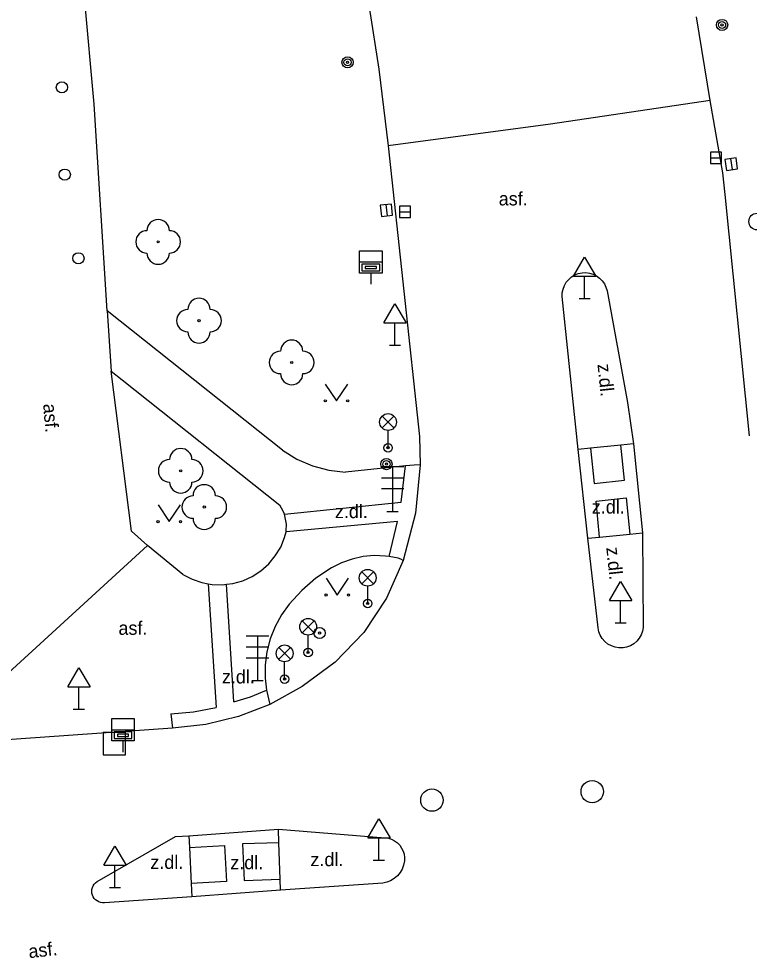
# Model space of a CAD drawing. Extents: x -642282 to -641982, y -1041678 to -1041427.
# Drawn here: x -642202.75 to -642170.13, y -1041575.81 to -1041533.81 of the extents above; entities that cross this region are included whole.
import ezdxf

# ---------------------------------------------------------------- set-up
doc = ezdxf.new("R2010")
doc.units = 0
for name, color, linetype in [('Popis povrchů', 7, 'Continuous'), ('Rozhraní ploch 1', 7, 'Continuous'), ('Rozhraní ploch 2', 7, 'Continuous'), ('Sloupy_označník', 7, 'Continuous'), ('Zeleň - stromy', 7, 'Continuous'), ('Znaky doprava', 7, 'Continuous'), ('Znaky kanalizace', 7, 'Continuous'), ('Znaky plyn', 7, 'Continuous'), ('Znaky voda', 7, 'Continuous'), ('Značky doprava', 7, 'Continuous'), ('Značky KM', 7, 'Continuous'), ('Šachty ner_', 7, 'Continuous')]:
    doc.layers.add(name, color=color, linetype=linetype)

msp = doc.modelspace()

# ---------------------------------------------------------------- linework, layer by layer
at = {"layer": 'Rozhraní ploch 1'}
for p, q in [((-642199.383, -1041537.636), (-642201.296, -1041516.368)), ((-642187.098, -1041533.3), (-642186.671, -1041536.073)), ((-642171.87, -1041537.46), (-642172.48, -1041533.728)), ((-642186.671, -1041536.073), (-642186.25, -1041539.49)), ((-642198.8, -1041546.87), (-642199.383, -1041537.636)), ((-642177.77, -1041553.07), (-642178.48, -1041546.23)), ((-642176.48, -1041545.98), (-642175.56, -1041550.96)), ((-642190.97, -1041553.1), (-642198.8, -1041546.87)), ((-642197.72, -1041556.72), (-642198.63, -1041549.56)), ((-642198.13, -1041549.95), (-642191.1, -1041555.56)), ((-642175.56, -1041550.96), (-642175.3, -1041552.81)), ((-642197.72, -1041556.72), (-642197.01, -1041557.36)), ((-642195.42, -1041558.65), (-642197.01, -1041557.36))]:
    msp.add_line(p, q, dxfattribs=at)
for points in [[(-642171.2, -1041541.67), (-642171.3, -1041540.7), (-642171.87, -1041537.46)], [(-642186.25, -1041539.49), (-642184.86, -1041552.48)], [(-642170.12, -1041552.46), (-642171.2, -1041541.67)], [(-642178.48, -1041546.23), (-642178.476, -1041546.061), (-642178.443, -1041545.896), (-642178.384, -1041545.738), (-642178.299, -1041545.592), (-642178.191, -1041545.463), (-642178.063, -1041545.353), (-642177.919, -1041545.266), (-642177.762, -1041545.204), (-642177.597, -1041545.169), (-642177.428, -1041545.162), (-642177.261, -1041545.184), (-642177.1, -1041545.232), (-642176.949, -1041545.307), (-642176.812, -1041545.406), (-642176.694, -1041545.527), (-642176.598, -1041545.665), (-642176.526, -1041545.818), (-642176.48, -1041545.98)], [(-642184.86, -1041552.48), (-642184.83, -1041553.75), (-642185.039, -1041555.919), (-642185.58, -1041558.03), (-642186.322, -1041559.713), (-642187.345, -1041561.243)], [(-642175.3, -1041552.81), (-642174.9, -1041556.79), (-642174.86, -1041561.02), (-642174.892, -1041561.192), (-642174.953, -1041561.355), (-642175.041, -1041561.506), (-642175.154, -1041561.639), (-642175.287, -1041561.752), (-642175.438, -1041561.839), (-642175.602, -1041561.9), (-642175.76, -1041561.93), (-642175.948, -1041561.933), (-642176.121, -1041561.905)], [(-642190.97, -1041553.1), (-642190.327, -1041553.493), (-642189.64, -1041553.79), (-642188.908, -1041553.988), (-642188.16, -1041554.08)], [(-642176.121, -1041561.905), (-642176.286, -1041561.848), (-642176.438, -1041561.763), (-642176.574, -1041561.654), (-642176.689, -1041561.522), (-642176.78, -1041561.373), (-642176.845, -1041561.211), (-642176.88, -1041561.04), (-642177.34, -1041557.03), (-642177.77, -1041553.07)], [(-642184.83, -1041553.75), (-642185.1, -1041553.76), (-642185.477, -1041553.799), (-642188.16, -1041554.08)], [(-642190.88, -1041557), (-642190.818, -1041556.743), (-642190.813, -1041556.706), (-642190.802, -1041556.404), (-642190.848, -1041556.106), (-642190.892, -1041555.958), (-642190.948, -1041555.821), (-642191.1, -1041555.56)], [(-642195.42, -1041558.65), (-642195.01, -1041558.866), (-642194.572, -1041559.017), (-642194.29, -1041559.07), (-642194.116, -1041559.1), (-642193.653, -1041559.114), (-642193.47, -1041559.09), (-642193.193, -1041559.058), (-642192.747, -1041558.933), (-642192.325, -1041558.742), (-642191.936, -1041558.49), (-642191.59, -1041558.182), (-642191.295, -1041557.826), (-642191.056, -1041557.429), (-642190.88, -1041557)], [(-642186.37, -1041557.83), (-642186.873, -1041557.81), (-642187.375, -1041557.854), (-642187.867, -1041557.962), (-642188.341, -1041558.131), (-642188.79, -1041558.36)], [(-642185.81, -1041557.92), (-642186.209, -1041557.856), (-642186.37, -1041557.83)], [(-642185.58, -1041558.03), (-642185.689, -1041557.962), (-642185.81, -1041557.92)], [(-642188.79, -1041558.36), (-642189.479, -1041558.825), (-642190.108, -1041559.368), (-642190.67, -1041559.98)], [(-642190.67, -1041559.98), (-642191.016, -1041560.462), (-642191.3, -1041560.983), (-642191.518, -1041561.535), (-642191.667, -1041562.11), (-642191.744, -1041562.698), (-642191.749, -1041563.292), (-642191.691, -1041563.821), (-642191.681, -1041563.882), (-642191.54, -1041564.458)], [(-642187.345, -1041561.243), (-642188.617, -1041562.572), (-642190.1, -1041563.66), (-642191.54, -1041564.458), (-642192.94, -1041565), (-642194.398, -1041565.356), (-642195.89, -1041565.52)], [(-642195.89, -1041565.52), (-642211.74, -1041566.64)], [(-642199.26, -1041572.38), (-642195.76, -1041570.37), (-642195.16, -1041570.33), (-642191.16, -1041570.04)], [(-642191.16, -1041570.04), (-642186.39, -1041570.42), (-642186.242, -1041570.444), (-642186.099, -1041570.491), (-642185.965, -1041570.561), (-642185.845, -1041570.65)], [(-642185.845, -1041570.65), (-642185.74, -1041570.758), (-642185.654, -1041570.881), (-642185.588, -1041571.017), (-642185.545, -1041571.161), (-642185.526, -1041571.31), (-642185.53, -1041571.46), (-642185.566, -1041571.643), (-642185.631, -1041571.818), (-642185.725, -1041571.979), (-642185.844, -1041572.123), (-642185.985, -1041572.245), (-642186.144, -1041572.341), (-642186.318, -1041572.411), (-642186.5, -1041572.45), (-642191.06, -1041572.77)], [(-642191.06, -1041572.77), (-642195.02, -1041573.06), (-642198.93, -1041573.33), (-642199.015, -1041573.33), (-642199.1, -1041573.316), (-642199.181, -1041573.288), (-642199.256, -1041573.247), (-642199.323, -1041573.195), (-642199.381, -1041573.132), (-642199.428, -1041573.061), (-642199.463, -1041572.983), (-642199.484, -1041572.9), (-642199.491, -1041572.815), (-642199.485, -1041572.73), (-642199.464, -1041572.647), (-642199.431, -1041572.568), (-642199.384, -1041572.496), (-642199.327, -1041572.433), (-642199.26, -1041572.38)]]:
    msp.add_lwpolyline(points, dxfattribs=at)
at = {"layer": 'Rozhraní ploch 2'}
for p, q in [((-642185.68, -1041555.42), (-642185.477, -1041553.799)), ((-642190.892, -1041555.958), (-642185.68, -1041555.42)), ((-642197.01, -1041557.36), (-642203.39, -1041563.21)), ((-642194.29, -1041559.07), (-642193.94, -1041564.6)), ((-642193.15, -1041564.35), (-642193.47, -1041559.09)), ((-642195.96, -1041564.88), (-642195.89, -1041565.52))]:
    msp.add_line(p, q, dxfattribs=at)
for points in [[(-642171.87, -1041537.46), (-642179, -1041538.53)], [(-642179, -1041538.53), (-642186.25, -1041539.49)], [(-642198.8, -1041546.87), (-642198.63, -1041549.56), (-642198.13, -1041549.95)], [(-642175.3, -1041552.81), (-642175.865, -1041552.87), (-642177.215, -1041553.012), (-642177.77, -1041553.07)], [(-642177.215, -1041553.012), (-642177.05, -1041554.58), (-642175.7, -1041554.44), (-642175.865, -1041552.87)], [(-642176.812, -1041556.978), (-642176.97, -1041555.37), (-642175.62, -1041555.23), (-642175.461, -1041556.845)], [(-642186.209, -1041557.856), (-642185.84, -1041556.28), (-642190.818, -1041556.743)], [(-642177.34, -1041557.03), (-642176.812, -1041556.978), (-642175.461, -1041556.845), (-642174.9, -1041556.79)], [(-642193.15, -1041564.35), (-642192.406, -1041564.126), (-642191.691, -1041563.821)], [(-642195.96, -1041564.88), (-642194.943, -1041564.79), (-642193.94, -1041564.6)], [(-642191.06, -1041572.77), (-642191.078, -1041572.271), (-642191.138, -1041570.641), (-642191.16, -1041570.04)], [(-642195.16, -1041570.33), (-642195.133, -1041570.851), (-642195.051, -1041572.461), (-642195.02, -1041573.06)], [(-642195.133, -1041570.851), (-642193.56, -1041570.77), (-642193.48, -1041572.38), (-642195.051, -1041572.461)], [(-642191.138, -1041570.641), (-642192.76, -1041570.7), (-642192.69, -1041572.33), (-642191.078, -1041572.271)]]:
    msp.add_lwpolyline(points, dxfattribs=at)
at = {"layer": 'Sloupy_označník'}
for centre, radius in [((-642171.34, -1041534.09), 0.25), ((-642171.34, -1041534.09), 0.158), ((-642171.34, -1041534.09), 0.05), ((-642188.07, -1041535.76), 0.25), ((-642188.07, -1041535.76), 0.158), ((-642188.07, -1041535.76), 0.05), ((-642186.33, -1041553.72), 0.25), ((-642186.33, -1041553.72), 0.158), ((-642186.33, -1041553.72), 0.05), ((-642189.32, -1041561.27), 0.25), ((-642189.32, -1041561.27), 0.05)]:
    msp.add_circle(centre, radius, dxfattribs=at)
at = {"layer": 'Zeleň - stromy'}
for centre in [(-642196.528, -1041543.786), (-642194.704, -1041547.309), (-642190.564, -1041549.177), (-642195.52, -1041554.02), (-642194.47, -1041555.64)]:
    msp.add_circle(centre, 0.05, dxfattribs=at)
for centre, start, end in [((-642196.528, -1041543.286), 0, 180), ((-642197.028, -1041543.786), 90, 270), ((-642196.028, -1041543.786), 270, 90), ((-642196.528, -1041544.286), 180, 0), ((-642194.704, -1041546.809), 0, 180), ((-642195.204, -1041547.309), 90, 270), ((-642194.204, -1041547.309), 270, 90), ((-642194.704, -1041547.809), 180, 0), ((-642190.564, -1041548.677), 0, 180), ((-642191.064, -1041549.177), 90, 270), ((-642190.064, -1041549.177), 270, 90), ((-642190.564, -1041549.677), 180, 0), ((-642195.52, -1041553.52), 0, 180), ((-642196.02, -1041554.02), 90, 270), ((-642195.02, -1041554.02), 270, 90), ((-642195.52, -1041554.52), 180, 0), ((-642194.47, -1041555.14), 0, 180), ((-642194.97, -1041555.64), 90, 270), ((-642193.97, -1041555.64), 270, 90), ((-642194.47, -1041556.14), 180, 0)]:
    msp.add_arc(centre, 0.5, start, end, dxfattribs=at)
at = {"layer": 'Znaky doprava'}
for p, q in [((-642186.525, -1041551.575), (-642185.995, -1041552.105)), ((-642186.525, -1041552.105), (-642185.995, -1041551.575)), ((-642186.26, -1041552.99), (-642186.26, -1041552.215)), ((-642186.558, -1041553.831), (-642185.558, -1041553.831)), ((-642186.058, -1041553.831), (-642186.058, -1041555.831)), ((-642186.558, -1041554.331), (-642185.558, -1041554.331)), ((-642185.558, -1041554.831), (-642186.558, -1041554.831)), ((-642186.308, -1041555.831), (-642185.808, -1041555.831)), ((-642187.435, -1041558.535), (-642186.905, -1041559.065)), ((-642187.435, -1041559.065), (-642186.905, -1041558.535)), ((-642187.17, -1041559.95), (-642187.17, -1041559.175)), ((-642190.095, -1041560.725), (-642189.565, -1041561.255)), ((-642190.095, -1041561.255), (-642189.565, -1041560.725)), ((-642189.83, -1041562.14), (-642189.83, -1041561.365)), ((-642192.59, -1041561.39), (-642191.59, -1041561.39)), ((-642192.09, -1041561.39), (-642192.09, -1041563.39)), ((-642192.59, -1041561.89), (-642191.59, -1041561.89)), ((-642191.145, -1041561.915), (-642190.615, -1041562.445)), ((-642191.145, -1041562.445), (-642190.615, -1041561.915)), ((-642191.59, -1041562.39), (-642192.59, -1041562.39)), ((-642190.88, -1041563.33), (-642190.88, -1041562.555)), ((-642192.34, -1041563.39), (-642191.84, -1041563.39))]:
    msp.add_line(p, q, dxfattribs=at)
for centre, radius in [((-642169.77, -1041542.88), 0.375), ((-642186.26, -1041551.84), 0.375), ((-642186.26, -1041552.99), 0.19), ((-642186.26, -1041552.99), 0.05), ((-642187.17, -1041558.8), 0.375), ((-642187.17, -1041559.95), 0.19), ((-642187.17, -1041559.95), 0.05), ((-642189.83, -1041560.99), 0.375), ((-642190.88, -1041562.18), 0.375), ((-642189.83, -1041562.14), 0.19), ((-642189.83, -1041562.14), 0.05), ((-642190.88, -1041563.33), 0.19), ((-642190.88, -1041563.33), 0.05)]:
    msp.add_circle(centre, radius, dxfattribs=at)
at = {"layer": 'Znaky kanalizace'}
for p, q in [((-642171.86, -1041540.03), (-642171.36, -1041540.03)), ((-642170.966, -1041540.063), (-642170.894, -1041540.557)), ((-642186.356, -1041542.121), (-642186.304, -1041542.619)), ((-642185.75, -1041542.44), (-642185.25, -1041542.44))]:
    msp.add_line(p, q, dxfattribs=at)
for points in [[(-642171.86, -1041540.28), (-642171.36, -1041540.28), (-642171.36, -1041539.78), (-642171.86, -1041539.78)], [(-642171.213, -1041540.098), (-642171.142, -1041540.593), (-642170.647, -1041540.522), (-642170.718, -1041540.027)], [(-642186.605, -1041542.148), (-642186.552, -1041542.645), (-642186.055, -1041542.592), (-642186.108, -1041542.095)], [(-642185.75, -1041542.69), (-642185.25, -1041542.69), (-642185.25, -1041542.19), (-642185.75, -1041542.19)]]:
    msp.add_lwpolyline(points, close=True, dxfattribs=at)
for centre in [(-642177.14, -1041568.36), (-642184.3, -1041568.74)]:
    msp.add_circle(centre, 0.5, dxfattribs=at)
at = {"layer": 'Znaky plyn'}
msp.add_circle((-642200.7, -1041540.78), 0.25, dxfattribs=at)
at = {"layer": 'Znaky voda'}
for p, q in [((-642187.03, -1041545.18), (-642187.03, -1041545.68)), ((-642198.1, -1041566.09), (-642198.1, -1041566.59))]:
    msp.add_line(p, q, dxfattribs=at)
for points in [[(-642187.53, -1041544.68), (-642187.53, -1041544.18), (-642186.53, -1041544.18), (-642186.53, -1041544.68)], [(-642186.53, -1041544.68), (-642186.53, -1041545.18), (-642187.53, -1041545.18), (-642187.53, -1041544.68), (-642186.53, -1041544.68)], [(-642198.6, -1041565.59), (-642198.6, -1041565.09), (-642197.6, -1041565.09), (-642197.6, -1041565.59)], [(-642197.6, -1041565.59), (-642197.6, -1041566.09), (-642198.6, -1041566.09), (-642198.6, -1041565.59), (-642197.6, -1041565.59)]]:
    msp.add_lwpolyline(points, dxfattribs=at)
for points in [[(-642187.43, -1041545.08), (-642186.63, -1041545.08), (-642186.63, -1041544.78), (-642187.43, -1041544.78)], [(-642187.28, -1041544.98), (-642186.78, -1041544.98), (-642186.78, -1041544.88), (-642187.28, -1041544.88)], [(-642198.5, -1041565.99), (-642197.7, -1041565.99), (-642197.7, -1041565.69), (-642198.5, -1041565.69)], [(-642198.35, -1041565.89), (-642197.85, -1041565.89), (-642197.85, -1041565.79), (-642198.35, -1041565.79)]]:
    msp.add_lwpolyline(points, close=True, dxfattribs=at)
for centre in [(-642200.83, -1041536.88), (-642200.09, -1041544.52)]:
    msp.add_circle(centre, 0.25, dxfattribs=at)
at = {"layer": 'Značky doprava'}
for p, q in [((-642177.98, -1041545.32), (-642177.48, -1041544.47)), ((-642177.48, -1041544.47), (-642176.98, -1041545.32)), ((-642177.98, -1041545.32), (-642176.98, -1041545.32)), ((-642177.48, -1041546.32), (-642177.48, -1041545.32)), ((-642186.45, -1041547.41), (-642185.95, -1041546.56)), ((-642185.95, -1041546.56), (-642185.45, -1041547.41)), ((-642177.729, -1041546.32), (-642177.231, -1041546.32)), ((-642186.45, -1041547.41), (-642185.45, -1041547.41)), ((-642185.95, -1041548.41), (-642185.95, -1041547.41)), ((-642186.2, -1041548.41), (-642185.7, -1041548.41)), ((-642176.37, -1041559.82), (-642175.87, -1041558.97)), ((-642175.87, -1041558.97), (-642175.37, -1041559.82)), ((-642176.37, -1041559.82), (-642175.37, -1041559.82)), ((-642175.87, -1041560.82), (-642175.87, -1041559.82)), ((-642176.119, -1041560.82), (-642175.621, -1041560.82)), ((-642200.57, -1041563.68), (-642200.07, -1041562.83)), ((-642200.07, -1041562.83), (-642199.57, -1041563.68)), ((-642200.57, -1041563.68), (-642199.57, -1041563.68)), ((-642200.07, -1041564.68), (-642200.07, -1041563.68)), ((-642200.319, -1041564.68), (-642199.821, -1041564.68)), ((-642187.17, -1041570.43), (-642186.67, -1041569.58)), ((-642186.67, -1041569.58), (-642186.17, -1041570.43)), ((-642187.17, -1041570.43), (-642186.17, -1041570.43)), ((-642186.67, -1041571.43), (-642186.67, -1041570.43)), ((-642198.96, -1041571.64), (-642198.46, -1041570.79)), ((-642198.46, -1041570.79), (-642197.96, -1041571.64)), ((-642186.919, -1041571.43), (-642186.421, -1041571.43)), ((-642198.96, -1041571.64), (-642197.96, -1041571.64)), ((-642198.46, -1041572.64), (-642198.46, -1041571.64)), ((-642198.709, -1041572.64), (-642198.211, -1041572.64))]:
    msp.add_line(p, q, dxfattribs=at)
at = {"layer": 'Značky KM'}
for p, q in [((-642189.062, -1041550.14), (-642188.562, -1041550.89)), ((-642188.562, -1041550.89), (-642188.062, -1041550.14)), ((-642196.531, -1041555.54), (-642196.031, -1041556.29)), ((-642196.031, -1041556.29), (-642195.531, -1041555.54)), ((-642189.026, -1041558.824), (-642188.526, -1041559.574)), ((-642188.526, -1041559.574), (-642188.026, -1041558.824))]:
    msp.add_line(p, q, dxfattribs=at)
for centre in [(-642189.062, -1041550.89), (-642188.062, -1041550.89), (-642196.531, -1041556.29), (-642195.531, -1041556.29), (-642189.026, -1041559.574), (-642188.026, -1041559.574)]:
    msp.add_circle(centre, 0.05, dxfattribs=at)
at = {"layer": 'Šachty ner_'}
msp.add_lwpolyline([(-642198.99, -1041566.71), (-642197.99, -1041566.71), (-642197.99, -1041565.71), (-642198.99, -1041565.71)], close=True, dxfattribs=at)

# ---------------------------------------------------------------- texts
at = {"layer": 'Popis povrchů'}
for s, p in [('asf.', (-642181.317, -1041542.158)), ('z.dl.', (-642188.634, -1041556.136)), ('z.dl.', (-642177.16, -1041555.928)), ('asf.', (-642198.301, -1041561.35)), ('z.dl.', (-642193.682, -1041563.525)), ('z.dl.', (-642196.877, -1041571.813)), ('z.dl.', (-642193.305, -1041571.828)), ('z.dl.', (-642189.727, -1041571.691))]:
    msp.add_text(s, height=0.6, dxfattribs=at).set_placement(p)
for s, rotation, p in [('z.dl.', 275.9261, (-642176.907, -1041549.264)), ('asf.', 274.8204, (-642201.668, -1041551.039)), ('z.dl.', 275.9261, (-642176.515, -1041557.454)), ('asf.', 6.5477, (-642202.29, -1041575.808))]:
    msp.add_text(s, height=0.6, rotation=rotation, dxfattribs=at).set_placement(p)

doc.saveas('drawing.dxf')
